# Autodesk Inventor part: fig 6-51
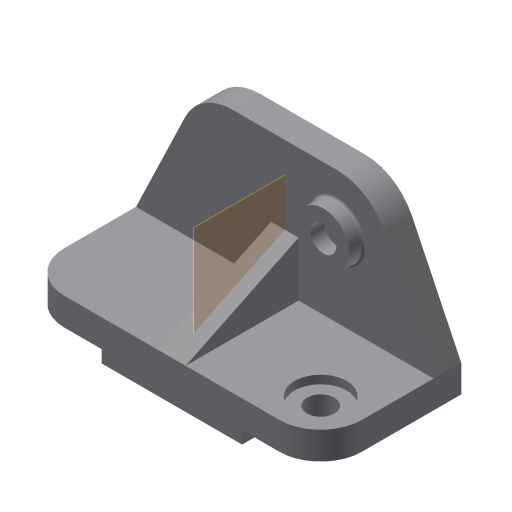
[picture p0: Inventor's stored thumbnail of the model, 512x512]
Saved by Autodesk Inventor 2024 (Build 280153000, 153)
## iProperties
Shininess: 77.0
Length Units: 11269
Angle Units: 11279
Time Units: 11290
Mass Units: 11283
Length Display Precision: 3
Angle Display Precision: 2
Created: 2001-12
Part Number: fig 6-51
Document SubType Name: Modeling
Designer: Renu Muthoo
Density: 1 g/cm^3
Material: Generic
Appearance: Default
Density: 0.0
Volumn: 0.0
Area: 0.0
PropertySet Name: Model Information
Control State: 0
Master: False
Checked Out: False
Author: Renu Muthoo
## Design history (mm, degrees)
sketch "Sketch2"
  geometry: L1 (-67.219, 19.116)-(148.781, 19.116); L2 (148.781, 19.116)-(148.781, -0.884); L3 (-67.219, -0.884)-(-67.219, 19.116); L4 (-10.219, -0.884)-(-10.219, -9.884); L5 (-10.219, -9.884)-(91.781, -9.884); L6 (91.781, -9.884)-(91.781, -0.884); L7 (148.781, -0.884)-(91.781, -0.884); L8 (-10.219, -0.884)-(-67.219, -0.884)
  constraints: 16 end point, 5 parallel, 4 perpendicular, 2 equal length, 1 horizontal
  dimensions: "d0" = 102 distance of L4.end L5.end; "d1" = 57 distance of L4.start L3.start; "d2" = 29 distance between parallel lines of L1 L5; "d3" = 20 distance of L1.end L2.end
extrude "Extrusion1" new body sketch "Sketch2" distance "d4" = 102; taper "d5" = 0 deg
sketch "Sketch3"
  geometry: L1 (67.219, -19.116)-(-148.781, -19.116) reference; L2 (67.219, -19.116)-(31.475, -93.564); L3 (-2.781, -115.116)-(-78.781, -115.116); L4 (-113.038, -93.564)-(-148.781, -19.116); A1 r 38 centre (-2.781, -77.116) between (-2.781, -115.116) and (31.475, -93.564); A2 r 38 centre (-78.781, -77.116) between (-113.038, -93.564) and (-78.781, -115.116)
  constraints: 6 end point, 4 point on circle, 4 tangent, 2 centre point, 1 equal length, 1 equal radius, 1 parallel
  dimensions: "d6" = 96 distance between parallel lines of L3 L1; "d7" = 38 radius of A1; "d8" = 76 distance of A2.centre A1.centre
extrude "Extrusion2" join sketch "Sketch3" distance "d9" = 20; taper "d10" = 0 deg
fillet "Fillet1" dims "d11" = 30
workplane "Work Plane1"
sketch "Sketch5"
  geometry: A1 r 30 centre (-30, 0) between (-30, -30) and (0, 0) reference; 1 further point
  constraints: 1 coincident
hole "Hole1" sketch "Sketch5" diameter "d16" = 20; stored, may be unused: countersink angle "d20" = 82 deg, drill point angle "d22" = 118 deg; dims "d17" = 6, "d18" = 38, "d19" = 6, "d21" = 8
sketch "Sketch6"
  geometry: C1 r 19 at (-2.781, 77.116); C2 r 9.5 at (-2.781, 77.116); A1 r 38 centre (-2.781, 77.116) between (31.475, 93.564) and (-2.781, 115.116) reference
  constraints: 2 centre point, 2 coincident
  dimensions: "d23" = 38 diameter of C1; "d24" = 19 diameter of C2
extrude "Extrusion3" join sketch "Sketch6" distance "d25" = 10; taper "d26" = 0 deg
sketch "Sketch7"
  geometry: L1 (0, -82)-(-39.557, 0); L2 (0, -82)-(20, -82) reference; L3 (29, 22.405)-(29, -82); L4 (29, -82)-(0, -82); L5 (0, -82)-(0, 0); L6 (0, 0)-(-90.034, 0); L7 (-90.034, 0)-(-90.034, 22.405); L8 (-90.034, 22.405)-(29, 22.405); L9 (0, 0)-(-74.447, 0) reference
  constraints: 14 end point, 1 collinear, 1 point on line
feature "Rib3" sketch "Sketch7" dims "d35" = 10, "d36" = 20
fillet "Fillet3" dims "d37" = 2
body "Solid1"
node "Sketch1"
other parameters: "d12" = -108
